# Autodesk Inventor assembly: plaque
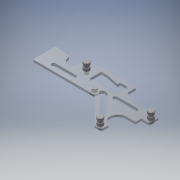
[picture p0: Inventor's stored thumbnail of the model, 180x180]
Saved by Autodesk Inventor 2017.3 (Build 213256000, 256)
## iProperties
Created: 2007-11
Part Number: plaque
Material: Générique
Document SubType Name: Assembly
Designer: ficho
Author: ficho
Sending System: SolidWorks 2009
Last Author: christophe
Last Saved: 2011-02-10
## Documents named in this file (4)
- G:\travail\année 2019-2020\réforme\toussaint\Serrure biométrique SET\Documentations_pedagogique\Modelisation_Solidworks\plaque.iam
- G:\travail\année 2019-2020\réforme\toussaint\Serrure biométrique SET\Documentations_pedagogique\Modelisation_Solidworks\Pièce8.ipt
- G:\travail\année 2019-2020\réforme\toussaint\Serrure biométrique SET\Documentations_pedagogique\Modelisation_Solidworks\Pièce9.ipt
- G:\travail\année 2019-2020\réforme\toussaint\Serrure biométrique SET\Documentations_pedagogique\Modelisation_Solidworks\Pièce10.ipt
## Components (5 placed, 3 different names)
1. Pièce8:1
2. Pièce9:1
3. Pièce9:2
4. Pièce9:3
5. Pièce10:1
